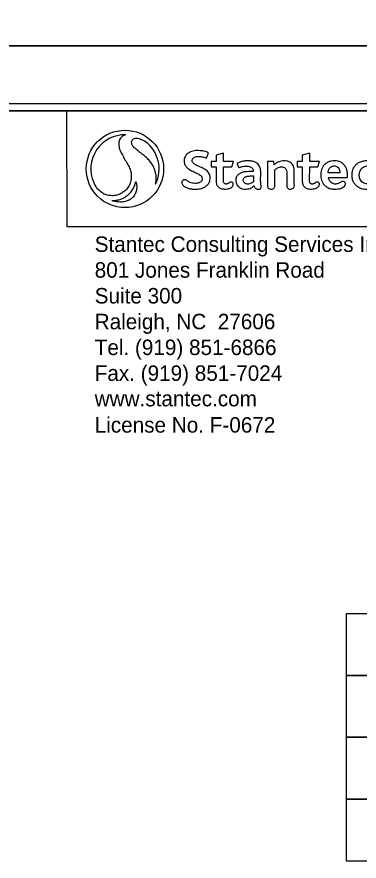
# Model space of a CAD drawing. Extents: x 2320980 to 2456309, y 595047 to 606177.
# Drawn here: x 2455975.9 to 2455999.5, y 596247.3 to 596305.6 of the extents above; entities that cross this region are included whole.
import ezdxf

# ---------------------------------------------------------------- set-up
doc = ezdxf.new("R2010")
doc.units = 0
for name, color, linetype in [('Prop Dimension', 7, 'Continuous'), ('Scratch_Level_0', 7, 'Continuous'), ('Sheet Data Text CELL', 7, 'Continuous'), ('Sheet Plan CELL', 7, 'Continuous'), ('Sheet Plot Border Inside CELL', 7, 'Continuous'), ('Sheet Plot Border Outside CELL', 7, 'Continuous')]:
    doc.layers.add(name, color=color, linetype=linetype)

msp = doc.modelspace()

# ---------------------------------------------------------------- linework, layer by layer
at = {"layer": 'Prop Dimension'}
for points in [[(2455998.637, 596264.366), (2456042.107, 596264.366), (2456042.107, 596260.09), (2455998.637, 596260.09)], [(2455998.637, 596260.09), (2456042.106, 596260.09), (2456042.106, 596255.814), (2455998.637, 596255.814)], [(2455998.637, 596255.814), (2456042.106, 596255.814), (2456042.106, 596251.538), (2455998.637, 596251.538)], [(2455998.637, 596251.538), (2456042.106, 596251.538), (2456042.106, 596247.262), (2455998.637, 596247.262)]]:
    msp.add_lwpolyline(points, close=True, dxfattribs=at)
at = {"layer": 'Scratch_Level_0'}
msp.add_lwpolyline([(2455979.323, 596299.076), (2456002.097, 596299.079), (2456002.098, 596291.07), (2455979.324, 596291.067)], close=True, dxfattribs=at)
at = {"layer": 'Sheet Data Text CELL'}
for p, q in [((2455988.965, 596295.819), (2455989.095, 596296.192)), ((2455990.145, 596296.169), (2455989.619, 596296.022)), ((2455989.619, 596296.022), (2455989.619, 596295.585)), ((2455990.145, 596295.585), (2455990.145, 596296.169)), ((2455996.092, 596296.17), (2455995.566, 596296.023)), ((2455995.566, 596296.023), (2455995.566, 596295.586)), ((2455996.092, 596295.586), (2455996.092, 596296.17)), ((2455989.619, 596295.585), (2455989.285, 596295.585)), ((2455989.285, 596295.585), (2455989.285, 596295.219)), ((2455989.285, 596295.219), (2455989.623, 596295.219)), ((2455990.135, 596294.294), (2455990.142, 596295.219)), ((2455990.142, 596295.219), (2455990.699, 596295.219)), ((2455990.826, 596295.585), (2455990.145, 596295.585)), ((2455990.699, 596295.219), (2455990.826, 596295.585)), ((2455991.046, 596295.451), (2455991.206, 596295.141)), ((2455993.606, 596295.584), (2455993.163, 596295.584)), ((2455993.163, 596295.584), (2455993.163, 596293.906)), ((2455993.635, 596295.362), (2455993.606, 596295.584)), ((2455995.566, 596295.586), (2455995.231, 596295.586)), ((2455995.231, 596295.586), (2455995.231, 596295.22)), ((2455995.231, 596295.22), (2455995.57, 596295.22)), ((2455996.082, 596294.295), (2455996.089, 596295.22)), ((2455996.089, 596295.22), (2455996.645, 596295.22)), ((2455996.773, 596295.586), (2455996.092, 596295.586)), ((2455996.645, 596295.22), (2455996.773, 596295.586)), ((2455993.679, 596293.906), (2455993.679, 596295.014)), ((2455998.174, 596294.803), (2455997.371, 596294.803)), ((2455992.195, 596294.591), (2455992.196, 596294.176)), ((2455997.371, 596294.481), (2455998.707, 596294.481))]:
    msp.add_line(p, q, dxfattribs=at)
for points in [[(2455983.379, 596297.428), (2455983.379, 596297.428)], [(2455984.732, 596296.965), (2455984.732, 596296.965)]]:
    msp.add_lwpolyline(points, dxfattribs=at)
msp.add_circle((2455983.328, 596295.072), 2.673, dxfattribs=at)
for start, end in [(88.77376, 203.69163), (88.76731, 88.77376), (333.78865, 53.43978), (247.12556, 251.46513)]:
    msp.add_arc((2455983.328, 596295.072), 2.357, start, end, dxfattribs=at)
for points, degree in [([(2455983.379, 596297.428), (2455983.322, 596297.416), (2455983.188, 596297.388), (2455983.013, 596297.209), (2455982.883, 596296.916), (2455982.9, 596296.587), (2455983.016, 596296.269), (2455983.192, 596295.96), (2455983.374, 596295.619), (2455983.576, 596295.297), (2455983.716, 596294.97), (2455983.782, 596294.614), (2455983.739, 596294.258), (2455983.635, 596293.931), (2455983.434, 596293.634), (2455983.17, 596293.423), (2455982.894, 596293.299), (2455982.644, 596293.222), (2455982.365, 596293.222), (2455982.055, 596293.265), (2455981.749, 596293.405), (2455981.423, 596293.681), (2455981.266, 596293.952), (2455981.17, 596294.125)], 3), ([(2455983.379, 596297.428), (2455983.379, 596297.428), (2455983.379, 596297.428), (2455983.379, 596297.428)], 2), ([(2455985.442, 596294.031), (2455985.463, 596294.114), (2455985.498, 596294.269), (2455985.491, 596294.518), (2455985.467, 596294.737), (2455985.403, 596294.94), (2455985.327, 596295.175), (2455985.194, 596295.43), (2455985.004, 596295.67), (2455984.756, 596295.923), (2455984.446, 596296.148), (2455984.127, 596296.409), (2455983.871, 596296.601), (2455983.781, 596296.827), (2455983.78, 596296.999), (2455983.865, 596297.115), (2455983.978, 596297.196), (2455984.129, 596297.21), (2455984.307, 596297.176), (2455984.513, 596297.089), (2455984.655, 596297.009), (2455984.732, 596296.965)], 3), ([(2455989.095, 596296.192), (2455989.072, 596296.203), (2455988.968, 596296.253), (2455988.77, 596296.305), (2455988.527, 596296.335), (2455988.306, 596296.346), (2455988.121, 596296.328), (2455987.945, 596296.291), (2455987.775, 596296.224), (2455987.611, 596296.111), (2455987.493, 596295.961), (2455987.426, 596295.809), (2455987.411, 596295.667), (2455987.418, 596295.536), (2455987.446, 596295.411), (2455987.499, 596295.308), (2455987.563, 596295.215), (2455987.642, 596295.13), (2455987.738, 596295.053), (2455987.856, 596294.982), (2455988.003, 596294.906), (2455988.165, 596294.832), (2455988.33, 596294.762), (2455988.466, 596294.692), (2455988.566, 596294.607), (2455988.635, 596294.527), (2455988.659, 596294.429), (2455988.656, 596294.336), (2455988.618, 596294.233), (2455988.533, 596294.148), (2455988.398, 596294.09), (2455988.238, 596294.066), (2455988.06, 596294.074), (2455987.903, 596294.107), (2455987.776, 596294.17), (2455987.673, 596294.212), (2455987.604, 596294.277), (2455987.538, 596294.302), (2455987.478, 596294.328), (2455987.413, 596294.324), (2455987.348, 596294.304), (2455987.293, 596294.256), (2455987.257, 596294.188), (2455987.254, 596294.113), (2455987.265, 596294.039), (2455987.323, 596293.961), (2455987.435, 596293.849), (2455987.633, 596293.752), (2455987.878, 596293.687), (2455988.127, 596293.674), (2455988.341, 596293.68), (2455988.528, 596293.704), (2455988.692, 596293.754), (2455988.863, 596293.831), (2455989.027, 596293.96), (2455989.154, 596294.12), (2455989.208, 596294.309), (2455989.215, 596294.479), (2455989.194, 596294.633), (2455989.133, 596294.757), (2455989.06, 596294.881), (2455988.932, 596294.986), (2455988.787, 596295.083), (2455988.627, 596295.16), (2455988.454, 596295.241), (2455988.274, 596295.318), (2455988.121, 596295.399), (2455988.018, 596295.492), (2455987.974, 596295.583), (2455987.966, 596295.678), (2455987.994, 596295.765), (2455988.053, 596295.841), (2455988.135, 596295.895), (2455988.243, 596295.934), (2455988.372, 596295.944), (2455988.5, 596295.939), (2455988.627, 596295.919), (2455988.75, 596295.892), (2455988.865, 596295.858), (2455988.934, 596295.831), (2455988.965, 596295.819)], 3), ([(2455989.623, 596295.219), (2455989.621, 596294.892), (2455989.62, 596294.547), (2455989.624, 596294.162), (2455989.641, 596294.07), (2455989.677, 596293.944), (2455989.749, 596293.858), (2455989.821, 596293.791), (2455989.898, 596293.74), (2455990.02, 596293.698), (2455990.188, 596293.679), (2455990.362, 596293.687), (2455990.536, 596293.711), (2455990.668, 596293.778), (2455990.765, 596293.856), (2455990.81, 596293.946), (2455990.815, 596294.025), (2455990.801, 596294.092), (2455990.766, 596294.131), (2455990.724, 596294.156), (2455990.675, 596294.165), (2455990.623, 596294.166), (2455990.57, 596294.152), (2455990.523, 596294.114), (2455990.47, 596294.074), (2455990.405, 596294.046), (2455990.336, 596294.024), (2455990.264, 596294.032), (2455990.202, 596294.066), (2455990.154, 596294.114), (2455990.133, 596294.197), (2455990.134, 596294.256), (2455990.135, 596294.294)], 3), ([(2455992.247, 596293.915), (2455992.248, 596293.897), (2455992.252, 596293.854), (2455992.295, 596293.79), (2455992.357, 596293.718), (2455992.469, 596293.666), (2455992.587, 596293.67), (2455992.697, 596293.694), (2455992.74, 596293.781), (2455992.742, 596293.868), (2455992.717, 596293.985), (2455992.69, 596294.307), (2455992.71, 596294.647), (2455992.704, 596295.015), (2455992.662, 596295.193), (2455992.562, 596295.353), (2455992.454, 596295.476), (2455992.276, 596295.566), (2455992.056, 596295.623), (2455991.795, 596295.64), (2455991.531, 596295.614), (2455991.277, 596295.555), (2455991.121, 596295.485), (2455991.046, 596295.451)], 3), ([(2455991.206, 596295.141), (2455991.23, 596295.154), (2455991.303, 596295.193), (2455991.422, 596295.23), (2455991.566, 596295.267), (2455991.702, 596295.276), (2455991.844, 596295.271), (2455991.972, 596295.231), (2455992.083, 596295.167), (2455992.161, 596295.074), (2455992.194, 596294.979), (2455992.194, 596294.92), (2455992.194, 596294.901)], 3), ([(2455993.679, 596295.014), (2455993.687, 596295.022), (2455993.723, 596295.055), (2455993.809, 596295.107), (2455993.921, 596295.181), (2455994.063, 596295.224), (2455994.207, 596295.223), (2455994.346, 596295.178), (2455994.441, 596295.079), (2455994.493, 596294.961), (2455994.52, 596294.801), (2455994.503, 596294.562), (2455994.515, 596294.259), (2455994.499, 596294.006), (2455994.51, 596293.832), (2455994.57, 596293.738), (2455994.675, 596293.672), (2455994.797, 596293.674), (2455994.913, 596293.702), (2455995.008, 596293.774), (2455995.035, 596293.912), (2455995.015, 596294.156), (2455995.028, 596294.456), (2455995.021, 596294.786), (2455995.033, 596294.996), (2455995.005, 596295.178), (2455994.948, 596295.306), (2455994.857, 596295.437), (2455994.711, 596295.54), (2455994.527, 596295.627), (2455994.317, 596295.632), (2455994.128, 596295.621), (2455993.958, 596295.565), (2455993.807, 596295.495), (2455993.706, 596295.415), (2455993.653, 596295.375), (2455993.635, 596295.362)], 3), ([(2455995.57, 596295.22), (2455995.568, 596294.892), (2455995.567, 596294.548), (2455995.57, 596294.163), (2455995.588, 596294.07), (2455995.624, 596293.944), (2455995.695, 596293.859), (2455995.768, 596293.792), (2455995.844, 596293.741), (2455995.967, 596293.698), (2455996.135, 596293.68), (2455996.309, 596293.687), (2455996.482, 596293.711), (2455996.614, 596293.778), (2455996.711, 596293.857), (2455996.757, 596293.947), (2455996.762, 596294.026), (2455996.747, 596294.092), (2455996.712, 596294.132), (2455996.671, 596294.156), (2455996.621, 596294.165), (2455996.569, 596294.166), (2455996.517, 596294.153), (2455996.47, 596294.115), (2455996.417, 596294.075), (2455996.351, 596294.047), (2455996.282, 596294.025), (2455996.211, 596294.033), (2455996.149, 596294.067), (2455996.1, 596294.115), (2455996.08, 596294.198), (2455996.081, 596294.257), (2455996.082, 596294.295)], 3), ([(2455998.707, 596294.481), (2455998.709, 596294.532), (2455998.713, 596294.66), (2455998.69, 596294.866), (2455998.638, 596295.097), (2455998.527, 596295.275), (2455998.402, 596295.429), (2455998.243, 596295.538), (2455998.041, 596295.618), (2455997.815, 596295.633), (2455997.593, 596295.629), (2455997.382, 596295.562), (2455997.201, 596295.459), (2455997.044, 596295.309), (2455996.937, 596295.128), (2455996.877, 596294.929), (2455996.854, 596294.726), (2455996.851, 596294.507), (2455996.9, 596294.305), (2455996.98, 596294.108), (2455997.102, 596293.939), (2455997.288, 596293.805), (2455997.519, 596293.691), (2455997.788, 596293.677), (2455998.033, 596293.679), (2455998.241, 596293.724), (2455998.405, 596293.803), (2455998.524, 596293.907), (2455998.568, 596294.019), (2455998.548, 596294.11), (2455998.503, 596294.183), (2455998.431, 596294.203), (2455998.36, 596294.213), (2455998.278, 596294.187), (2455998.181, 596294.126), (2455998.07, 596294.059), (2455997.934, 596294.028), (2455997.808, 596294.025), (2455997.684, 596294.057), (2455997.581, 596294.128), (2455997.479, 596294.211), (2455997.419, 596294.323), (2455997.382, 596294.413), (2455997.374, 596294.464), (2455997.371, 596294.481)], 3), ([(2455997.371, 596294.803), (2455997.371, 596294.82), (2455997.371, 596294.861), (2455997.376, 596294.939), (2455997.402, 596295.04), (2455997.465, 596295.146), (2455997.562, 596295.231), (2455997.695, 596295.278), (2455997.837, 596295.282), (2455997.97, 596295.241), (2455998.083, 596295.169), (2455998.139, 596295.046), (2455998.167, 596294.922), (2455998.172, 596294.84), (2455998.174, 596294.803)], 3), ([(2456000.686, 596295.475), (2456000.642, 596295.5), (2456000.532, 596295.561), (2456000.319, 596295.617), (2456000.053, 596295.645), (2455999.77, 596295.612), (2455999.499, 596295.524), (2455999.276, 596295.374), (2455999.115, 596295.172), (2455999.015, 596294.938), (2455998.98, 596294.676), (2455999.001, 596294.411), (2455999.091, 596294.174), (2455999.225, 596293.992), (2455999.411, 596293.833), (2455999.666, 596293.714), (2455999.965, 596293.667), (2456000.239, 596293.685), (2456000.466, 596293.745), (2456000.645, 596293.827), (2456000.762, 596293.94), (2456000.768, 596294.047), (2456000.758, 596294.127), (2456000.704, 596294.176), (2456000.649, 596294.209), (2456000.588, 596294.213), (2456000.506, 596294.2), (2456000.433, 596294.136), (2456000.326, 596294.091), (2456000.22, 596294.041), (2456000.067, 596294.029), (2455999.908, 596294.043), (2455999.755, 596294.126), (2455999.64, 596294.242), (2455999.548, 596294.38), (2455999.52, 596294.544), (2455999.496, 596294.706), (2455999.542, 596294.866), (2455999.604, 596295.013), (2455999.695, 596295.13), (2455999.818, 596295.217), (2455999.958, 596295.272), (2456000.122, 596295.285), (2456000.286, 596295.27), (2456000.443, 596295.22), (2456000.529, 596295.16), (2456000.57, 596295.131)], 3), ([(2455992.194, 596294.901), (2455992.16, 596294.9), (2455992.05, 596294.898), (2455991.859, 596294.889), (2455991.632, 596294.877), (2455991.42, 596294.83), (2455991.224, 596294.749), (2455991.053, 596294.602), (2455990.973, 596294.394), (2455990.984, 596294.198), (2455991.016, 596294.03), (2455991.118, 596293.888), (2455991.266, 596293.758), (2455991.478, 596293.679), (2455991.698, 596293.676), (2455991.902, 596293.702), (2455992.057, 596293.757), (2455992.172, 596293.835), (2455992.22, 596293.887), (2455992.247, 596293.915)], 3), ([(2455982.412, 596292.901), (2455982.47, 596292.895), (2455982.606, 596292.882), (2455982.84, 596292.927), (2455983.101, 596292.988), (2455983.336, 596293.125), (2455983.552, 596293.277), (2455983.755, 596293.495), (2455983.923, 596293.737), (2455984.03, 596293.99), (2455984.062, 596294.139), (2455984.078, 596294.21)], 3), ([(2455984.078, 596294.21), (2455984.095, 596294.15), (2455984.139, 596293.997), (2455984.15, 596293.741), (2455984.106, 596293.463), (2455983.963, 596293.211), (2455983.771, 596292.979), (2455983.491, 596292.852), (2455983.194, 596292.784), (2455982.888, 596292.779), (2455982.679, 596292.819), (2455982.579, 596292.838)], 3), ([(2455992.196, 596294.176), (2455992.183, 596294.165), (2455992.134, 596294.128), (2455992.045, 596294.08), (2455991.92, 596294.028), (2455991.787, 596294.02), (2455991.672, 596294.05), (2455991.592, 596294.102), (2455991.54, 596294.163), (2455991.505, 596294.237), (2455991.5, 596294.316), (2455991.515, 596294.395), (2455991.562, 596294.47), (2455991.643, 596294.518), (2455991.739, 596294.561), (2455991.866, 596294.578), (2455991.996, 596294.585), (2455992.111, 596294.592), (2455992.171, 596294.591), (2455992.195, 596294.591)], 3), ([(2455993.163, 596293.906), (2455993.168, 596293.884), (2455993.179, 596293.834), (2455993.216, 596293.749), (2455993.31, 596293.677), (2455993.441, 596293.676), (2455993.573, 596293.686), (2455993.651, 596293.772), (2455993.679, 596293.847), (2455993.679, 596293.888), (2455993.679, 596293.906)], 3)]:
    msp.add_open_spline(points, degree=degree, dxfattribs=at)
at = {"layer": 'Sheet Plan CELL'}
for points in [[(2455742.104, 596089.076), (2455742.099, 596299.071), (2456002.097, 596299.079), (2456002.099, 596269.066), (2456042.107, 596269.064), (2456042.107, 596089.076)], [(2456042.112, 596299.076), (2455742.104, 596299.076), (2455742.104, 596089.076), (2456042.107, 596089.076)]]:
    msp.add_lwpolyline(points, close=True, dxfattribs=at)
at = {"layer": 'Sheet Plot Border Inside CELL'}
msp.add_lwpolyline([(2455711.407, 596088.574), (2456044.604, 596088.576), (2456044.607, 596299.574), (2455711.407, 596299.574)], close=True, dxfattribs=at)
at = {"layer": 'Sheet Plot Border Outside CELL'}
for points in [[(2455708.807, 596303.574), (2456045.507, 596303.574), (2456045.507, 596522.574), (2455708.807, 596522.574)], [(2455708.807, 596084.574), (2456045.507, 596084.574), (2456045.507, 596303.574), (2455708.807, 596303.574)]]:
    msp.add_lwpolyline(points, close=True, dxfattribs=at)

# ---------------------------------------------------------------- texts
at = {"layer": 'Sheet Data Text CELL'}
for s, height, p in [('Stantec Consulting Services Inc.', 1.06932, (2455981.236, 596289.34)), ('801 Jones Franklin Road', 1.06932, (2455981.236, 596287.559)), ('Suite 300', 1.0693, (2455981.236, 596285.777)), ('Raleigh, NC  27606', 1.06932, (2455981.236, 596283.996)), ('Tel. (919) 851-6866', 1.06932, (2455981.237, 596282.215)), ('Fax. (919) 851-7024', 1.06932, (2455981.237, 596280.433)), ('www.stantec.com', 1.06932, (2455981.237, 596278.673)), ('License No. F-0672', 1.06932, (2455981.237, 596276.857))]:
    msp.add_text(s, height=height, rotation=0.00714, dxfattribs=at).set_placement(p)

doc.saveas('drawing.dxf')
